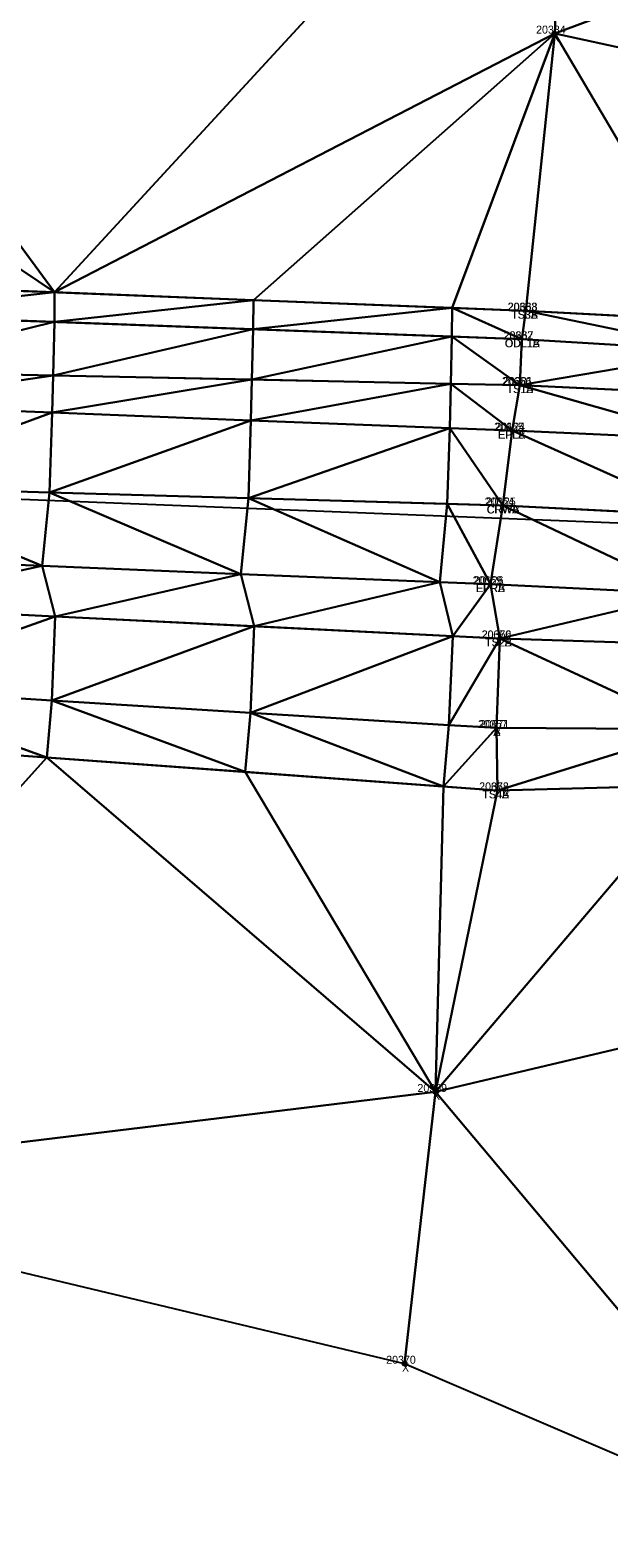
# Model space of a CAD drawing. Extents: x 1966740 to 1969291, y 1117379 to 1118460.
# Drawn here: x 1968470 to 1968542.7, y 1117786.6 to 1117976 of the extents above; entities that cross this region are included whole.
import ezdxf

# ---------------------------------------------------------------- set-up
doc = ezdxf.new("R2010")
doc.units = 0
for name, color, linetype in [('Level 1', 7, 'Continuous'), ('Level 3', 7, 'Continuous'), ('Level 30', 7, 'Continuous'), ('Level 35', 7, 'Continuous'), ('Level 50', 7, 'Continuous'), ('Level 52', 7, 'Continuous'), ('Level 53', 7, 'Continuous'), ('Level 56', 7, 'Continuous'), ('Level 6', 7, 'Continuous'), ('Level 62', 7, 'Continuous')]:
    doc.layers.add(name, color=color, linetype=linetype)

msp = doc.modelspace()

# ---------------------------------------------------------------- linework, layer by layer
at = {"layer": 'Level 1'}
msp.add_line((1968120.33, 1117930.94), (1969279.02, 1117884.95), dxfattribs=at)
at = {"layer": 'Level 3'}
for points in [[(1968378.68, 1117946.52), (1968423.07, 1117945.03), (1968532.27, 1117940.77)], [(1967874.77, 1117908.42), (1967879.51, 1117916.91), (1967881.27, 1117924.39), (1967885.24, 1117929.22), (1967913.7, 1117935.63), (1967966.11, 1117937.12), (1968012.39, 1117940.75), (1968059.42, 1117941.87), (1968105.44, 1117943.27), (1968158.32, 1117942.95), (1968212.48, 1117942.1), (1968371.25, 1117933.41), (1968422.85, 1117933.68), (1968531.49, 1117931.42)], [(1968532.27, 1117940.77), (1968682.68, 1117932.75), (1968784.38, 1117929.07), (1968872.44, 1117926.13)], [(1967878.98, 1117895.46), (1967875.66, 1117903.48), (1967919.49, 1117917.47), (1967966.4, 1117928.95), (1968012.66, 1117935.42), (1968058.94, 1117938.37), (1968105.99, 1117939.39), (1968158.7, 1117938.56), (1968212.05, 1117937.21), (1968318.79, 1117933.28), (1968422.76, 1117929.93), (1968530.54, 1117925.7)], [(1968531.49, 1117931.42), (1968682.06, 1117924.3), (1968783.42, 1117919.17), (1968888.7, 1117914.33), (1968991.06, 1117912.02), (1969093.07, 1117907.16), (1969191.83, 1117902.92), (1969283.72, 1117899.63)], [(1967878.98, 1117895.46), (1967922.07, 1117909.4), (1967968.89, 1117921.38), (1968013.49, 1117926.44), (1968059.29, 1117929.05), (1968105.63, 1117929.86), (1968159.12, 1117928.97), (1968212.65, 1117927.25), (1968318.5, 1117923.95), (1968422.42, 1117919.39), (1968529.36, 1117916.3)], [(1968530.54, 1117925.7), (1968681.97, 1117919.01), (1968783.23, 1117915.36), (1968888.64, 1117911.44), (1968991.22, 1117907.09), (1969091.98, 1117903.06), (1969191.09, 1117898.66), (1969283.27, 1117895.43)], [(1967878.98, 1117895.46), (1967883.11, 1117885.63), (1967924.99, 1117899.59), (1967970.68, 1117910.78), (1968014.42, 1117916.56), (1968059.13, 1117919.49), (1968105.39, 1117920.31), (1968159.16, 1117919.37), (1968212.5, 1117917.97), (1968317.55, 1117914.44), (1968421.52, 1117910.75), (1968527.82, 1117906.41)], [(1967884.1, 1117882.92), (1967891.06, 1117879.24), (1967898.84, 1117879.11), (1967924.17, 1117888.04), (1967954.33, 1117900.3), (1967970.81, 1117903.15), (1968012.93, 1117910.83), (1968059.62, 1117915.05), (1968105.25, 1117916.2), (1968157.57, 1117912.09), (1968210.74, 1117910.77), (1968320.32, 1117907.54), (1968423.18, 1117904.83), (1968528.99, 1117899.6)], [(1968529.36, 1117916.3), (1968681.48, 1117908.5), (1968781.89, 1117904.51), (1968887.49, 1117900.39), (1968989.06, 1117896.4), (1969090.87, 1117891.24), (1969190.23, 1117887.94), (1969284.4, 1117884.73)], [(1968527.82, 1117906.41), (1968680.79, 1117899.07), (1968781.71, 1117895.37), (1968887.86, 1117891.84), (1968988.65, 1117888.23), (1969090.1, 1117882.83), (1969189.3, 1117879.04), (1969282.94, 1117875.42)], [(1968528.99, 1117899.6), (1968680.45, 1117894.84), (1968781.74, 1117892.71), (1968887.7, 1117888.94), (1968987.81, 1117885.08), (1969089.75, 1117880.01), (1969189.02, 1117876.39), (1969282.76, 1117873.05)], [(1968058.02, 1117883.74), (1968104.17, 1117887.52), (1968156.67, 1117888.05), (1968209.1, 1117889.3), (1968320.79, 1117888.13), (1968422.17, 1117888.28), (1968528.68, 1117880.51)], [(1968528.68, 1117880.51), (1968680.3, 1117884.55), (1968781.05, 1117880.46), (1968887.57, 1117875.57), (1968986, 1117872.85), (1969087.95, 1117867.56), (1969189.32, 1117864.4), (1969289.73, 1117862.33)]]:
    msp.add_lwpolyline(points, dxfattribs=at)
at = {"layer": 'Level 30'}
for centre in [(1968535.88, 1117975.58), (1968520.9, 1117842.62), (1968517.02, 1117808.48)]:
    msp.add_circle(centre, 0.25, dxfattribs=at)
at = {"layer": 'Level 35'}
for points in [[(1968422.92, 1118011.27), (1968537.39, 1118012.98), (1968473.03, 1117943.08)], [(1968473.03, 1117943.08), (1968537.39, 1118012.98), (1968535.88, 1117975.58)], [(1968535.88, 1117975.58), (1968537.39, 1118012.98), (1968589.34, 1117995.59)], [(1968422.32, 1117977.2), (1968422.92, 1118011.27), (1968473.03, 1117943.08)], [(1968535.88, 1117975.58), (1968589.34, 1117995.59), (1968586.56, 1117964.56)], [(1968422.32, 1117977.2), (1968473.03, 1117943.08), (1968448.05, 1117944.05)], [(1968473.03, 1117943.08), (1968535.88, 1117975.58), (1968498.01, 1117942.11)], [(1968498.01, 1117942.11), (1968535.88, 1117975.58), (1968522.98, 1117941.14)], [(1968522.98, 1117941.14), (1968535.88, 1117975.58), (1968532.27, 1117940.77)], [(1968532.27, 1117940.77), (1968535.88, 1117975.58), (1968557.23, 1117939.44)], [(1968535.88, 1117975.58), (1968586.56, 1117964.56), (1968557.23, 1117939.44)], [(1968448.02, 1117940.27), (1968448.05, 1117944.05), (1968473.03, 1117943.08)], [(1968448.02, 1117940.27), (1968473.03, 1117943.08), (1968473, 1117939.35)], [(1968473, 1117939.35), (1968473.03, 1117943.08), (1968498.01, 1117942.11)], [(1968473, 1117939.35), (1968498.01, 1117942.11), (1968497.98, 1117938.43)], [(1968497.98, 1117938.43), (1968498.01, 1117942.11), (1968522.98, 1117941.14)], [(1968447.84, 1117933.16), (1968448.02, 1117940.27), (1968473, 1117939.35)], [(1968497.98, 1117938.43), (1968522.98, 1117941.14), (1968522.97, 1117937.51)], [(1968522.97, 1117937.51), (1968522.98, 1117941.14), (1968531.76, 1117937.18)], [(1968522.98, 1117941.14), (1968532.27, 1117940.77), (1968531.76, 1117937.18)], [(1968531.76, 1117937.18), (1968532.27, 1117940.77), (1968556.71, 1117935.68)], [(1968532.27, 1117940.77), (1968557.23, 1117939.44), (1968556.71, 1117935.68)], [(1968447.84, 1117933.16), (1968473, 1117939.35), (1968472.84, 1117932.64)], [(1968472.84, 1117932.64), (1968473, 1117939.35), (1968497.98, 1117938.43)], [(1968472.84, 1117932.64), (1968497.98, 1117938.43), (1968497.83, 1117932.12)], [(1968497.83, 1117932.12), (1968497.98, 1117938.43), (1968522.97, 1117937.51)], [(1968497.83, 1117932.12), (1968522.97, 1117937.51), (1968522.82, 1117931.6)], [(1968522.82, 1117931.6), (1968522.97, 1117937.51), (1968531.49, 1117931.42)], [(1968522.97, 1117937.51), (1968531.76, 1117937.18), (1968531.49, 1117931.42)], [(1968531.49, 1117931.42), (1968531.76, 1117937.18), (1968556.71, 1117935.68)], [(1968531.49, 1117931.42), (1968556.71, 1117935.68), (1968556.46, 1117930.24)], [(1968447.74, 1117928.95), (1968447.84, 1117933.16), (1968472.84, 1117932.64)], [(1968447.74, 1117928.95), (1968472.84, 1117932.64), (1968472.72, 1117927.97)], [(1968472.72, 1117927.97), (1968472.84, 1117932.64), (1968497.83, 1117932.12)], [(1968472.72, 1117927.97), (1968497.83, 1117932.12), (1968497.7, 1117926.99)], [(1968497.7, 1117926.99), (1968497.83, 1117932.12), (1968522.82, 1117931.6)], [(1968497.7, 1117926.99), (1968522.82, 1117931.6), (1968522.68, 1117926.01)], [(1968522.68, 1117926.01), (1968522.82, 1117931.6), (1968530.54, 1117925.7)], [(1968522.82, 1117931.6), (1968531.49, 1117931.42), (1968530.54, 1117925.7)], [(1968530.54, 1117925.7), (1968531.49, 1117931.42), (1968555.51, 1117924.6)], [(1968531.49, 1117931.42), (1968556.46, 1117930.24), (1968555.51, 1117924.6)], [(1968447.41, 1117918.67), (1968447.74, 1117928.95), (1968472.72, 1117927.97)], [(1968447.41, 1117918.67), (1968472.72, 1117927.97), (1968472.4, 1117917.95)], [(1968472.4, 1117917.95), (1968472.72, 1117927.97), (1968497.7, 1117926.99)], [(1968472.4, 1117917.95), (1968497.7, 1117926.99), (1968497.39, 1117917.23)], [(1968497.39, 1117917.23), (1968497.7, 1117926.99), (1968522.68, 1117926.01)], [(1968497.39, 1117917.23), (1968522.68, 1117926.01), (1968522.38, 1117916.51)], [(1968522.38, 1117916.51), (1968522.68, 1117926.01), (1968529.36, 1117916.3)], [(1968522.68, 1117926.01), (1968530.54, 1117925.7), (1968529.36, 1117916.3)], [(1968529.36, 1117916.3), (1968530.54, 1117925.7), (1968554.33, 1117915.02)], [(1968530.54, 1117925.7), (1968555.51, 1117924.6), (1968554.33, 1117915.02)], [(1968446.5, 1117909.73), (1968447.41, 1117918.67), (1968471.47, 1117908.71)], [(1968447.41, 1117918.67), (1968472.4, 1117917.95), (1968471.47, 1117908.71)], [(1968471.47, 1117908.71), (1968472.4, 1117917.95), (1968496.45, 1117907.69)], [(1968472.4, 1117917.95), (1968497.39, 1117917.23), (1968496.45, 1117907.69)], [(1968496.45, 1117907.69), (1968497.39, 1117917.23), (1968521.43, 1117906.67)], [(1968497.39, 1117917.23), (1968522.38, 1117916.51), (1968521.43, 1117906.67)], [(1968521.43, 1117906.67), (1968522.38, 1117916.51), (1968527.82, 1117906.41)], [(1968522.38, 1117916.51), (1968529.36, 1117916.3), (1968527.82, 1117906.41)], [(1968527.82, 1117906.41), (1968529.36, 1117916.3), (1968552.79, 1117905.21)], [(1968529.36, 1117916.3), (1968554.33, 1117915.02), (1968552.79, 1117905.21)], [(1968446.5, 1117909.73), (1968471.47, 1117908.71), (1968448.15, 1117903.59)], [(1968448.15, 1117903.59), (1968471.47, 1117908.71), (1968473.12, 1117902.36)], [(1968471.47, 1117908.71), (1968496.45, 1117907.69), (1968473.12, 1117902.36)], [(1968473.12, 1117902.36), (1968496.45, 1117907.69), (1968498.09, 1117901.12)], [(1968496.45, 1117907.69), (1968521.43, 1117906.67), (1968498.09, 1117901.12)], [(1968498.09, 1117901.12), (1968521.43, 1117906.67), (1968523.06, 1117899.89)], [(1968521.43, 1117906.67), (1968527.82, 1117906.41), (1968523.06, 1117899.89)], [(1968523.06, 1117899.89), (1968527.82, 1117906.41), (1968528.99, 1117899.6)], [(1968527.82, 1117906.41), (1968552.79, 1117905.21), (1968528.99, 1117899.6)], [(1968528.99, 1117899.6), (1968552.79, 1117905.21), (1968553.98, 1117898.81)], [(1968447.74, 1117893.37), (1968448.15, 1117903.59), (1968473.12, 1117902.36)], [(1968447.74, 1117893.37), (1968473.12, 1117902.36), (1968472.69, 1117891.82)], [(1968472.69, 1117891.82), (1968473.12, 1117902.36), (1968498.09, 1117901.12)], [(1968472.69, 1117891.82), (1968498.09, 1117901.12), (1968497.64, 1117890.27)], [(1968497.64, 1117890.27), (1968498.09, 1117901.12), (1968523.06, 1117899.89)], [(1968497.64, 1117890.27), (1968523.06, 1117899.89), (1968522.59, 1117888.72)], [(1968522.59, 1117888.72), (1968523.06, 1117899.89), (1968528.99, 1117899.6)], [(1968522.59, 1117888.72), (1968528.99, 1117899.6), (1968528.55, 1117888.35)], [(1968528.55, 1117888.35), (1968528.99, 1117899.6), (1968553.54, 1117888.2)], [(1968528.99, 1117899.6), (1968553.98, 1117898.81), (1968553.54, 1117888.2)], [(1968447.11, 1117886.46), (1968447.74, 1117893.37), (1968472.04, 1117884.64)], [(1968447.74, 1117893.37), (1968472.69, 1117891.82), (1968472.04, 1117884.64)], [(1968472.04, 1117884.64), (1968472.69, 1117891.82), (1968496.97, 1117882.82)], [(1968472.69, 1117891.82), (1968497.64, 1117890.27), (1968496.97, 1117882.82)], [(1968496.97, 1117882.82), (1968497.64, 1117890.27), (1968521.91, 1117881)], [(1968497.64, 1117890.27), (1968522.59, 1117888.72), (1968521.91, 1117881)], [(1968521.91, 1117881), (1968522.59, 1117888.72), (1968528.55, 1117888.35)], [(1968521.91, 1117881), (1968528.55, 1117888.35), (1968528.68, 1117880.51)], [(1968528.55, 1117888.35), (1968553.54, 1117888.2), (1968528.68, 1117880.51)], [(1968528.68, 1117880.51), (1968553.54, 1117888.2), (1968553.67, 1117881.17)], [(1968423.45, 1117830.77), (1968447.11, 1117886.46), (1968472.04, 1117884.64)], [(1968423.45, 1117830.77), (1968472.04, 1117884.64), (1968520.9, 1117842.62)], [(1968472.04, 1117884.64), (1968496.97, 1117882.82), (1968520.9, 1117842.62)], [(1968496.97, 1117882.82), (1968521.91, 1117881), (1968520.9, 1117842.62)], [(1968520.9, 1117842.62), (1968528.68, 1117880.51), (1968553.67, 1117881.17)], [(1968520.9, 1117842.62), (1968553.67, 1117881.17), (1968579.19, 1117856.4)], [(1968520.9, 1117842.62), (1968521.91, 1117881), (1968528.68, 1117880.51)], [(1968520.9, 1117842.62), (1968579.19, 1117856.4), (1968567.95, 1117786.61)], [(1968423.45, 1117830.77), (1968520.9, 1117842.62), (1968517.02, 1117808.48)], [(1968517.02, 1117808.48), (1968520.9, 1117842.62), (1968567.95, 1117786.61)]]:
    msp.add_lwpolyline(points, close=True, dxfattribs=at)
at = {"layer": 'Level 50'}
for centre in [(1968532.27, 1117940.77), (1968532.27, 1117940.77), (1968531.76, 1117937.18), (1968531.76, 1117937.18), (1968531.49, 1117931.42), (1968531.49, 1117931.42), (1968530.54, 1117925.7), (1968530.54, 1117925.7), (1968529.36, 1117916.3), (1968529.36, 1117916.3), (1968527.82, 1117906.41), (1968527.82, 1117906.41), (1968528.99, 1117899.6), (1968528.99, 1117899.6), (1968528.55, 1117888.35), (1968528.55, 1117888.35), (1968528.68, 1117880.51), (1968528.68, 1117880.51)]:
    msp.add_circle(centre, 0.001, dxfattribs=at)
at = {"layer": 'Level 6'}
for points in [[(1968380.83, 1117942.48), (1968423.04, 1117941.19), (1968531.76, 1117937.18)], [(1968531.76, 1117937.18), (1968682.22, 1117928.11), (1968784.28, 1117924.56), (1968890.2, 1117919.49), (1968991.22, 1117915.37), (1969093.76, 1117910.9), (1969192.08, 1117906.24), (1969283.24, 1117903.06)], [(1967868.28, 1117817.14), (1967892.54, 1117814.5), (1967928.24, 1117834.22), (1967973.92, 1117854.29), (1967982.67, 1117861.15), (1968021.78, 1117883.3), (1968056.97, 1117897.44), (1968105.42, 1117898.77), (1968155.9, 1117899.84), (1968209.66, 1117898.76), (1968320.81, 1117895.57), (1968422.79, 1117894.92), (1968528.55, 1117888.35)], [(1968528.55, 1117888.35), (1968679.78, 1117887.39), (1968780.67, 1117884.45), (1968887.36, 1117880.9), (1968987.02, 1117877.31), (1969088.58, 1117870.53), (1969189.53, 1117868.6), (1969284.94, 1117865.64)]]:
    msp.add_lwpolyline(points, dxfattribs=at)

# ---------------------------------------------------------------- texts
at = {"layer": 'Level 52'}
for s, p in [('20384', (1968533.54, 1117975.58)), ('20369', (1968518.63, 1117842.62)), ('20370', (1968514.7, 1117808.48))]:
    msp.add_text(s, height=1, dxfattribs=at).set_placement(p)
at = {"layer": 'Level 53'}
for s, p in [('20383', (1968529.95, 1117940.77)), ('20668', (1968530, 1117940.77)), ('TS3A', (1968530.4, 1117939.77)), ('TS3B', (1968530.45, 1117939.77)), ('20382', (1968529.44, 1117937.18)), ('20667', (1968529.48, 1117937.18)), ('ODL1A', (1968529.6, 1117936.18)), ('ODL1B', (1968529.65, 1117936.18)), ('20666', (1968529.24, 1117931.42)), ('20381', (1968529.39, 1117931.42)), ('TS1A', (1968529.83, 1117930.42)), ('TS1B', (1968529.88, 1117930.42)), ('20665', (1968528.27, 1117925.7)), ('20124', (1968528.41, 1117925.7)), ('EPLA', (1968528.74, 1117924.7)), ('EPLB', (1968528.79, 1117924.7)), ('20664', (1968527.07, 1117916.3)), ('20125', (1968527.26, 1117916.3)), ('CRWA', (1968527.32, 1117915.3)), ('CRWB', (1968527.38, 1117915.3)), ('20669', (1968525.57, 1117906.41)), ('20126', (1968525.74, 1117906.41)), ('EPRA', (1968525.97, 1117905.41)), ('EPRB', (1968526.02, 1117905.41)), ('20670', (1968526.69, 1117899.6)), ('20366', (1968526.72, 1117899.6)), ('TS2A', (1968527.12, 1117898.6)), ('TS2B', (1968527.17, 1117898.6)), ('20368', (1968526.39, 1117880.51)), ('20672', (1968526.38, 1117880.51)), ('TS4A', (1968526.78, 1117879.51)), ('TS4B', (1968526.83, 1117879.51))]:
    msp.add_text(s, height=1, dxfattribs=at).set_placement(p)
at = {"layer": 'Level 56'}
for s, p in [('20367', (1968526.25, 1117888.35)), ('20671', (1968526.46, 1117888.35)), ('A', (1968528.16, 1117887.35)), ('B', (1968528.21, 1117887.35))]:
    msp.add_text(s, height=1, dxfattribs=at).set_placement(p)
at = {"layer": 'Level 62'}
for p in [(1968535.54, 1117974.58), (1968520.57, 1117841.62), (1968516.69, 1117807.48)]:
    msp.add_text('X', height=1, dxfattribs=at).set_placement(p)

doc.saveas('drawing.dxf')
